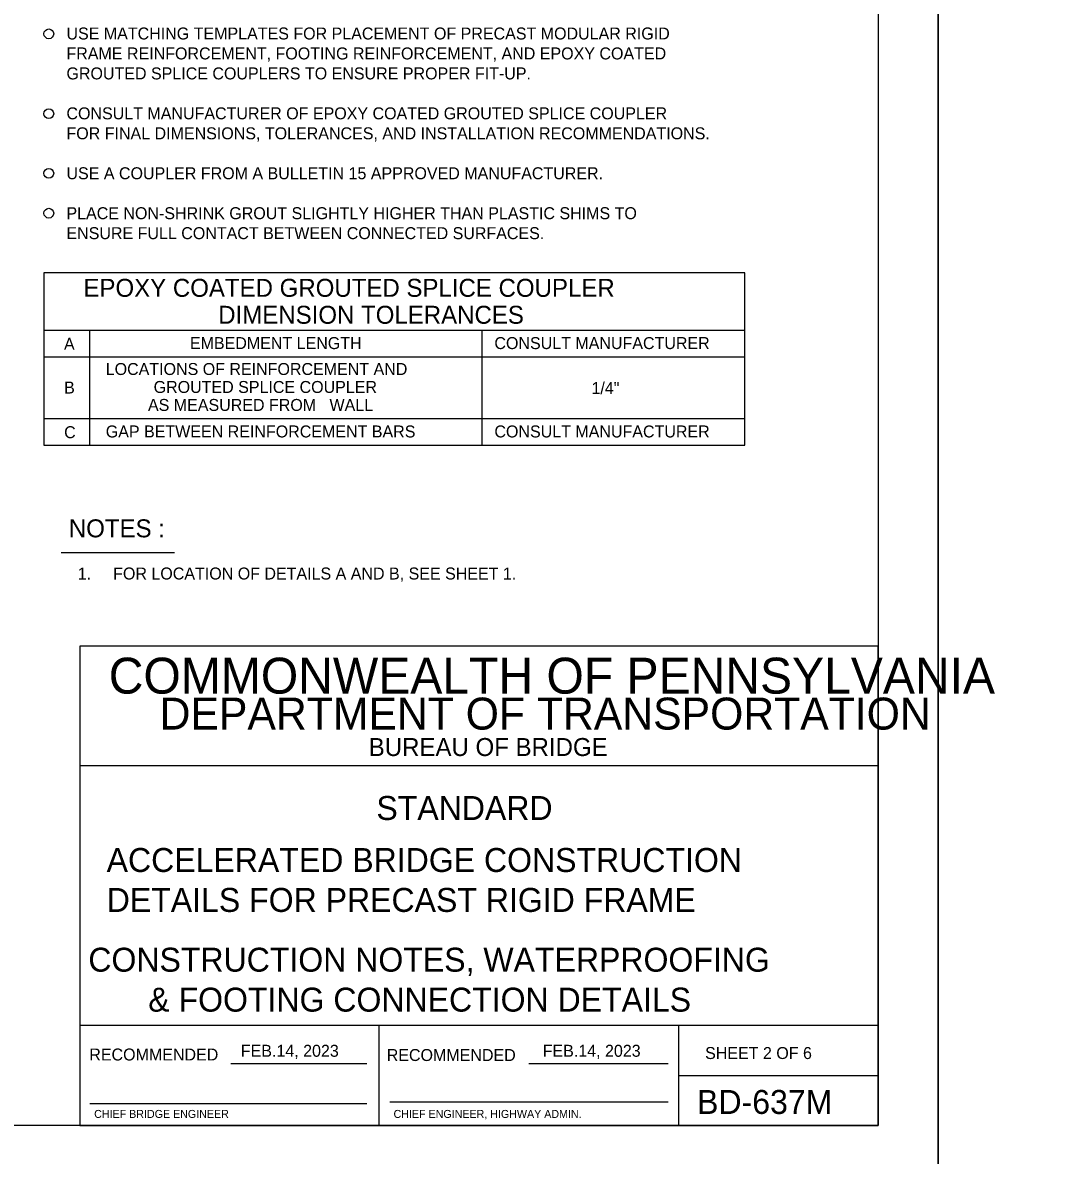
# Model space of a CAD drawing. Extents: x 641328 to 643024, y 298283 to 300065.
# Drawn here: x 641939.2 to 642195.6, y 298884.8 to 299168.4 of the extents above; entities that cross this region are included whole.
import ezdxf

# ---------------------------------------------------------------- set-up
doc = ezdxf.new("R2010")
doc.units = 0
for name, color, linetype in [('2', 7, 'Continuous'), ('DATES', 7, 'Continuous'), ('PLT-BNDY', 7, 'Continuous'), ('SIGNATORY TITLES', 7, 'Continuous')]:
    doc.layers.add(name, color=color, linetype=linetype)

msp = doc.modelspace()

# ---------------------------------------------------------------- linework, layer by layer
at = {"layer": '2'}
for p, q in [((642153.5, 299456.3), (642153.5, 298892.3)), ((641944.53, 299091.46), (642120.1, 299091.46)), ((641955.91, 299091.46), (641955.91, 299062.65)), ((642054.24, 299091.46), (642054.24, 299062.65)), ((641944.53, 299084.78), (642120.1, 299084.78)), ((641944.53, 299069.33), (642120.1, 299069.33)), ((641948.84, 299035.79), (641977.21, 299035.79)), ((642153.5, 299012.3), (641953.5, 299012.3)), ((641953.5, 299012.3), (641953.5, 298892.3)), ((642153.5, 298892.3), (642153.5, 299012.3)), ((642153.5, 298982.3), (641953.5, 298982.3)), ((642153.5, 298917.3), (641953.5, 298917.3)), ((642028.5, 298892.3), (642028.5, 298917.3)), ((642103.5, 298917.3), (642103.5, 298892.3)), ((641991.35, 298907.8), (642025.39, 298907.8)), ((642065.95, 298907.8), (642100.92, 298907.8)), ((642103.5, 298904.8), (642153.5, 298904.8)), ((641956, 298897.8), (642025.39, 298897.8)), ((642031.13, 298898.17), (642100.92, 298898.17)), ((642153.5, 298892.3), (641367.51, 298892.3)), ((641953.5, 298892.3), (642153.5, 298892.3))]:
    msp.add_line(p, q, dxfattribs=at)
for points in [[(641944.53, 299105.76), (641944.53, 299062.65)], [(642120.1, 299105.76), (641944.53, 299105.76)], [(642120.1, 299062.65), (642120.1, 299105.76)], [(641944.53, 299062.65), (642120.1, 299062.65)]]:
    msp.add_lwpolyline(points, dxfattribs=at)
for centre in [(641945.74, 299165.64), (641945.74, 299145.64), (641945.74, 299130.73), (641945.74, 299120.73)]:
    msp.add_circle(centre, 1.22, dxfattribs=at)
at = {"layer": 'PLT-BNDY'}
for points in [[(641327.51, 299471.3), (642168.51, 299471.3), (642168.51, 298877.3), (641327.51, 298877.3)], [(642168.51, 299471.3), (643009.51, 299471.3), (643009.51, 298877.3), (642168.51, 298877.3)]]:
    msp.add_lwpolyline(points, close=True, dxfattribs=at)

# ---------------------------------------------------------------- texts
at = {"layer": '2'}
for s, height, p in [('USE MATCHING TEMPLATES FOR PLACEMENT OF PRECAST MODULAR RIGID ', 3, (641950.16, 299164.23)), ('FRAME REINFORCEMENT, FOOTING REINFORCEMENT, AND EPOXY COATED ', 3, (641950.16, 299159.23)), ('GROUTED SPLICE COUPLERS TO ENSURE PROPER FIT-UP.', 3, (641950.16, 299154.23)), ('CONSULT MANUFACTURER OF EPOXY COATED GROUTED SPLICE COUPLER', 3, (641950.16, 299144.23)), ('FOR FINAL DIMENSIONS, TOLERANCES, AND INSTALLATION RECOMMENDATIONS.', 3, (641950.16, 299139.23)), ('USE A COUPLER FROM A BULLETIN 15 APPROVED MANUFACTURER.', 3, (641950.16, 299129.23)), ('PLACE NON-SHRINK GROUT SLIGHTLY HIGHER THAN PLASTIC SHIMS TO ', 3, (641950.16, 299119.23)), ('ENSURE FULL CONTACT BETWEEN CONNECTED SURFACES.', 3, (641950.16, 299114.23)), ('EPOXY COATED GROUTED SPLICE COUPLER', 4.5, (641954.41, 299099.79)), ('DIMENSION TOLERANCES', 4.5, (641988.18, 299093.04)), ('A', 3, (641949.54, 299086.52)), ('EMBEDMENT LENGTH', 3, (641981.08, 299086.7)), ('CONSULT MANUFACTURER', 3, (642057.36, 299086.7)), ('LOCATIONS OF REINFORCEMENT AND', 3, (641960, 299080.21)), ('B', 3, (641949.58, 299075.57)), ('GROUTED SPLICE COUPLER', 3, (641972, 299075.71)), ('  1/4"', 3, (642079.45, 299075.44)), ('AS MEASURED FROM   WALL', 3, (641970.58, 299071.21)), ('GAP BETWEEN REINFORCEMENT BARS', 3, (641960.01, 299064.57)), ('CONSULT MANUFACTURER', 3, (642057.36, 299064.57)), ('C', 3, (641949.58, 299064.39)), ('NOTES :', 4.5, (641950.76, 299039.56)), ('1.', 3, (641953, 299029)), ('FOR LOCATION OF DETAILS A AND B, SEE SHEET 1.', 3, (641961.86, 299029)), ('COMMONWEALTH OF PENNSYLVANIA', 9, (641960.75, 299000.42)), ('DEPARTMENT OF TRANSPORTATION', 8.0002, (641973.5, 298991.42)), ('BUREAU OF BRIDGE', 4.5, (642025.88, 298984.8)), ('STANDARD', 6, (642027.8, 298968.78)), ('ACCELERATED BRIDGE CONSTRUCTION', 6, (641960.23, 298955.76)), ('DETAILS FOR PRECAST RIGID FRAME', 6, (641960.25, 298945.76)), ('CONSTRUCTION NOTES, WATERPROOFING', 6, (641955.64, 298930.79)), ('& FOOTING CONNECTION DETAILS', 6, (641970.66, 298920.79)), ('SHEET 2 OF 6', 3, (642110.14, 298908.92)), ('BD-637M', 6, (642108.13, 298895.17))]:
    msp.add_text(s, height=height, dxfattribs=at).set_placement(p)
for p in [(641955.88, 298908.55), (642030.39, 298908.42)]:
    msp.add_text('RECOMMENDED', height=3, rotation=360, dxfattribs=at).set_placement(p)
at = {"layer": 'DATES'}
for p in [(641993.84, 298909.48), (642069.46, 298909.48)]:
    msp.add_text('FEB.14, 2023', height=3, dxfattribs=at).set_placement(p)
at = {"layer": 'SIGNATORY TITLES'}
for s, p in [('CHIEF BRIDGE ENGINEER', (641957.1, 298894.17)), ('CHIEF ENGINEER, HIGHWAY ADMIN.', (642032.1, 298894.17))]:
    msp.add_text(s, height=2, dxfattribs=at).set_placement(p)

doc.saveas('drawing.dxf')
